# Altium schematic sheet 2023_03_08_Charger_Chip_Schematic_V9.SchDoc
size A3; SheetNumber: 1; SheetTotal: 1
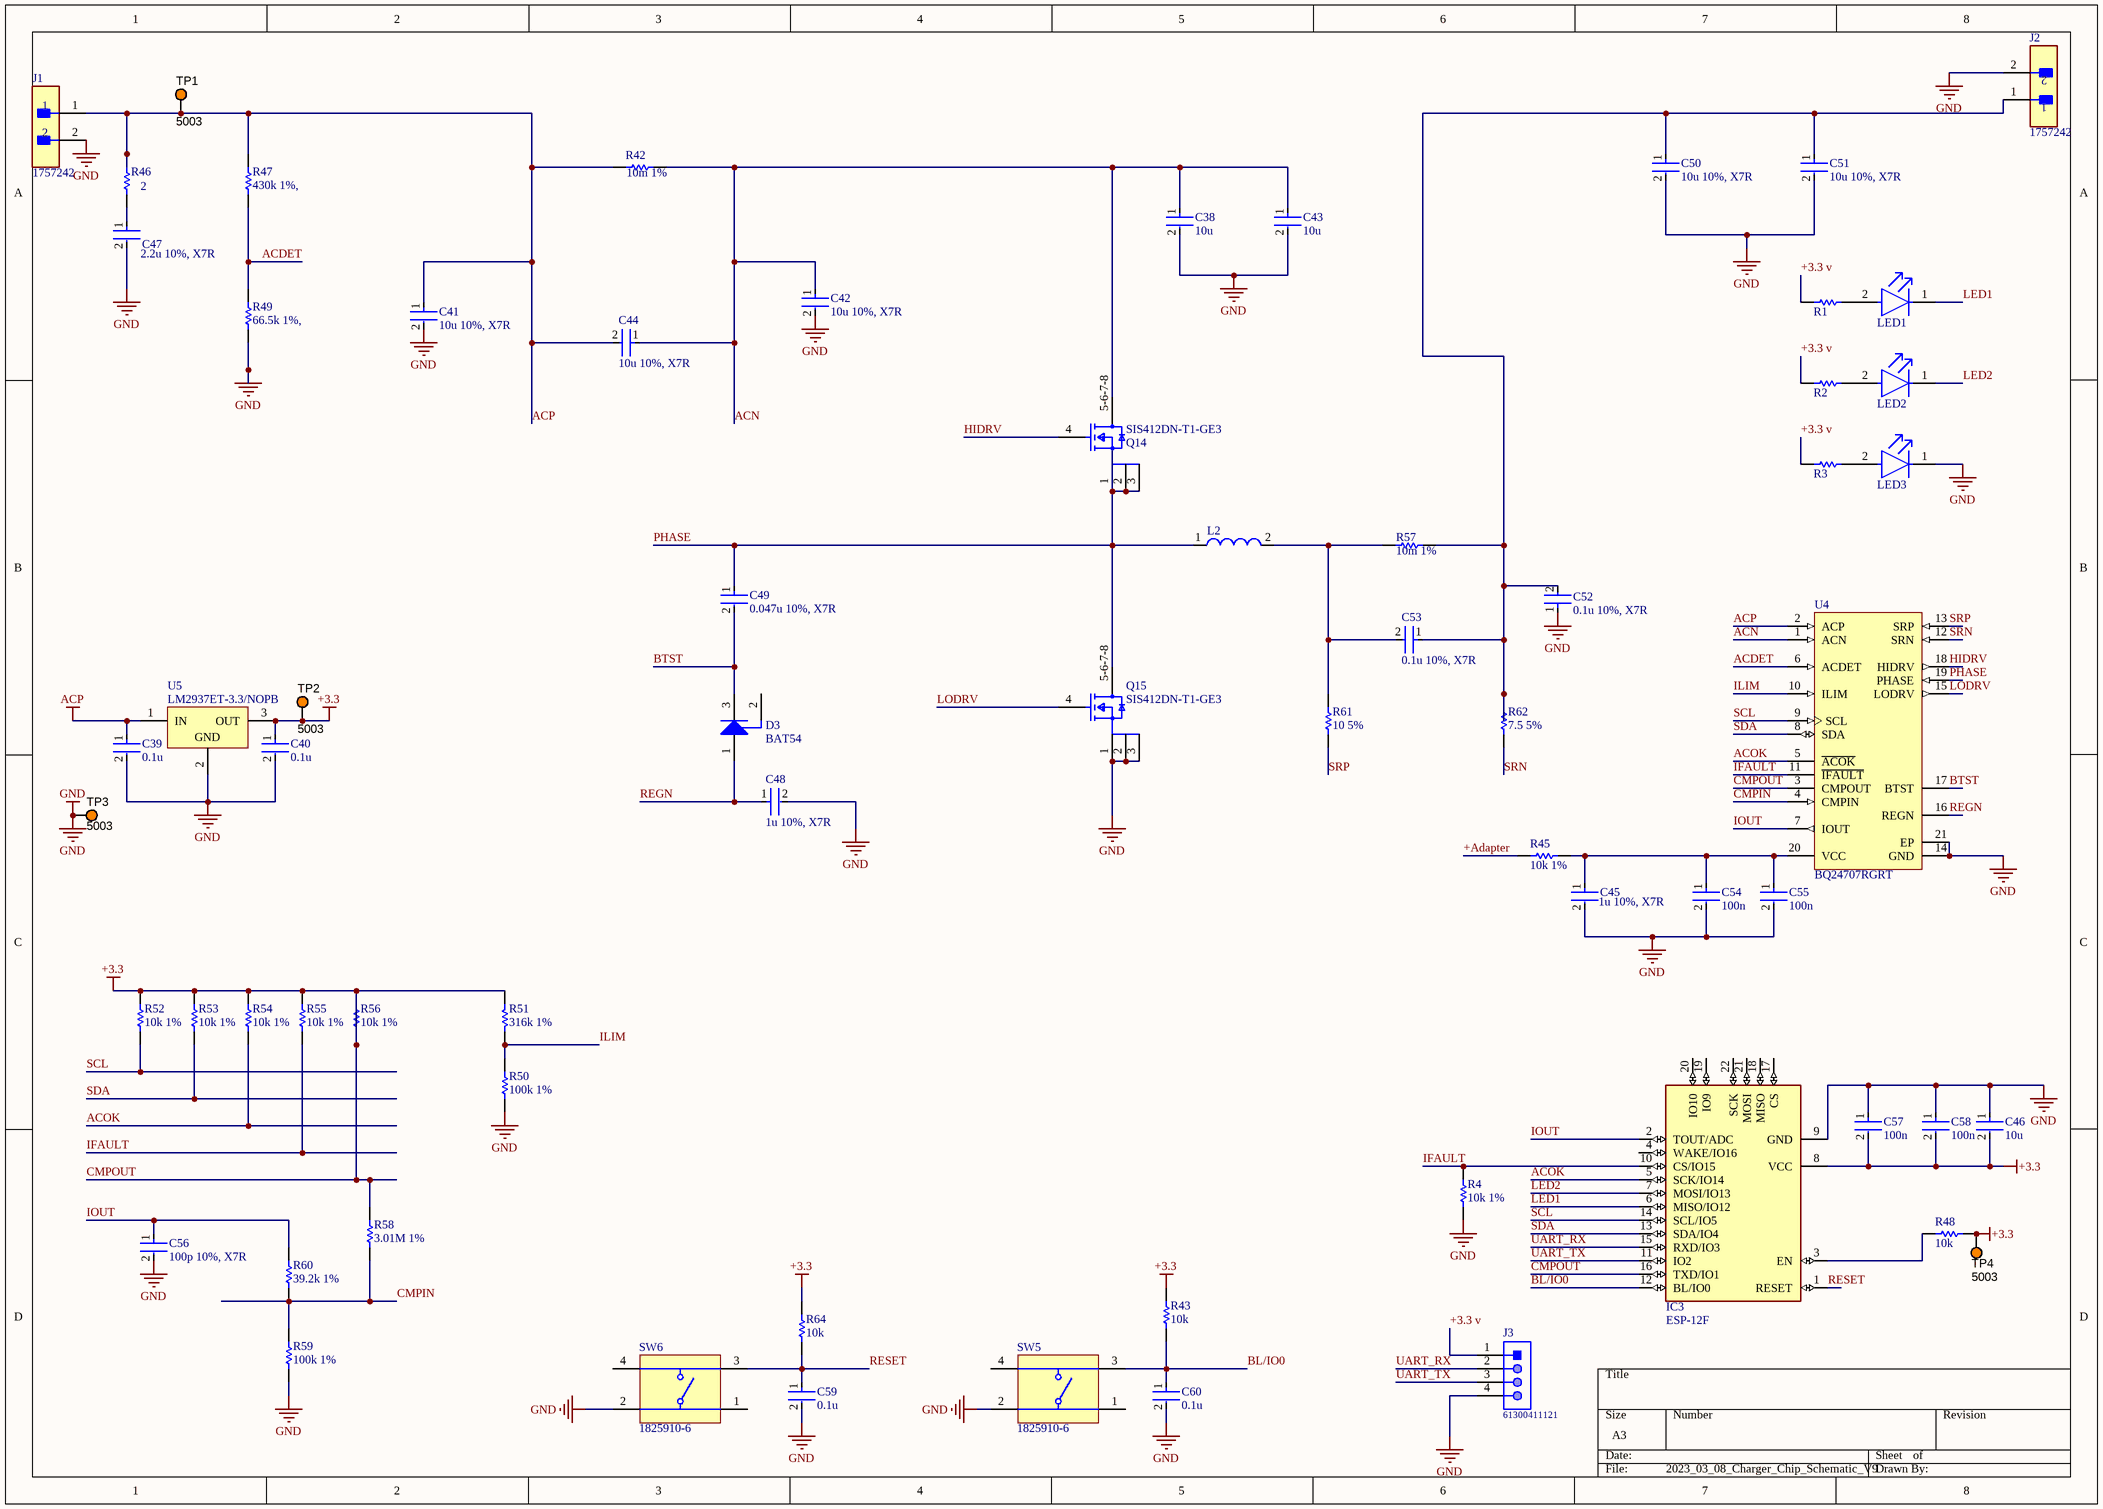
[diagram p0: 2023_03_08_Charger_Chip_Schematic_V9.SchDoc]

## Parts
C38  10u  [FP-C0603C-CF-MFG]
C39  0.1u  [FP-C0603C-CF-MFG]
C40  0.1u  [FP-C0603C-CF-MFG]
C41  10u 10%, X7R  [FP-C0603C-CF-MFG]
C42  10u 10%, X7R  [FP-C0603C-CF-MFG]
C43  10u  [FP-C0603C-CF-MFG]
C44  10u 10%, X7R  [FP-C0603C-CF-MFG]
C45  1u 10%, X7R  [FP-C0603C-CF-MFG]
C46  10u  [FP-C0603C-CF-MFG]
C47  2.2u 10%, X7R  [FP-1206-L_3_2_0_2-W_1_6_0-IPC_C]
C48  1u 10%, X7R  [FP-C0603C-CF-MFG]
C49  0.047u 10%, X7R  [FP-C0603C-CF-MFG]
C50  10u 10%, X7R  [FP-C0603C-CF-MFG]
C51  10u 10%, X7R  [FP-C0603C-CF-MFG]
C52  0.1u 10%, X7R  [FP-C0603C-CF-MFG]
C53  0.1u 10%, X7R  [FP-C0603C-CF-MFG]
C54  100n  [FP-C0603C-CF-MFG]
C55  100n  [FP-C0603C-CF-MFG]
C56  100p 10%, X7R  [FP-C0603C-CF-MFG]
C57  100n  [FP-C0603C-CF-MFG]
C58  100n  [FP-C0603C-CF-MFG]
C59  0.1u  [FP-C0603C-CF-MFG]
C60  0.1u  [FP-C0603C-CF-MFG]
D3  BAT54  [INF-SOT23_L]
IC3  ESP-12F  [ESP-12F]
J1  1757242  [FP-1757242-MFG]
J2  1757242  [FP-1757242-MFG]
J3  61300411121  [61300411121]
L2  744771004  [WE-PD-L]  (value not drawn)
LED1  APA1606SYCK  [FP-APA1606SYCK-MFG]  (value not drawn)
LED2  APA1606SYCK  [FP-APA1606SYCK-MFG]  (value not drawn)
LED3  APA1606SYCK  [FP-APA1606SYCK-MFG]  (value not drawn)
Q14  SIS412DN-T1-GE3  [FP-S16-2667-SINGLE-MFG]
Q15  SIS412DN-T1-GE3  [FP-S16-2667-SINGLE-MFG]
R1  CRCW060310K0FKEA  [RESC1609X50X30NL8T20]  (value not drawn)
R2  CRCW060310K0FKEA  [RESC1609X50X30NL8T20]  (value not drawn)
R3  CRCW060310K0FKEA  [RESC1609X50X30NL8T20]  (value not drawn)
R4  10k 1%  [RESC1609X50X30ML10T20]
R42  10m 1%  [RESC1609X50X30ML10T20]
R43  10k  [RESC1609X50X30ML10T20]
R45  10k 1%  [RESC1609X50X30ML10T20]
R46  2  [RESC1609X50X30ML10T20]
R47  430k 1%,  [RESC1609X50X30ML10T20]
R48  10k  [RESC1609X50X30ML10T20]
R49  66.5k 1%,  [RESC1609X50X30ML10T20]
R50  100k 1%  [RESC1609X50X30ML10T20]
R51  316k 1%  [RESC1609X50X30ML10T20]
R52  10k 1%  [RESC1609X50X30ML10T20]
R53  10k 1%  [RESC1609X50X30ML10T20]
R54  10k 1%  [RESC1609X50X30ML10T20]
R55  10k 1%  [RESC1609X50X30ML10T20]
R56  10k 1%  [RESC1609X50X30ML10T20]
R57  10m 1%  [RESC1609X50X30ML10T20]
R58  3.01M 1%  [RESC1609X50X30ML10T20]
R59  100k 1%  [RESC1609X50X30ML10T20]
R60  39.2k 1%  [RESC1609X50X30ML10T20]
R61  10 5%  [RESC1609X50X30ML10T20]
R62  7.5 5%  [RESC1609X50X30ML10T20]
R64  10k  [RESC1609X50X30ML10T20]
SW5  1825910-6  [TECO-1825910-6_V]
SW6  1825910-6  [TECO-1825910-6_V]
TP1  5003  [KSTN-5003]
TP2  5003  [KSTN-5003]
TP3  5003  [KSTN-5003]
TP4  5003  [KSTN-5003]
U4  BQ24707RGRT  [RGR0020A_V]
U5  LM2937ET-3.3/NOPB  [NDE0003A]

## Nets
ACP: C39.1 C41.1 C44.2 J1.1 R42.2 R46.2 R47.2 TP1.1 U4.2(ACP) U5.1(IN)
CMPOUT: C40.1 C46.2 C57.2 C58.2 IC3.8(VCC) IC3.16(TXD/IO1) R43.2 R48.1 R51.2 R52.2 R53.2 R54.2 R55.2 R56.1 R56.2 R58.2 R64.2 TP2.1 TP4.1 U4.3(CMPOUT) U5.3(OUT)  [also labelled +3.3]
GND: C38.2 C39.2 C40.2 C41.2 C42.2 C43.2 C45.2 C46.1 C47.2 C48.2 C50.2 C51.2 C52.1 C54.2 C55.2 C56.2 C57.1 C58.1 C59.2 C60.2 IC3.9(GND) J1.2 J2.2 J3.4 LED3.1(C) Q15.1(S) Q15.2(S) Q15.3(S) R4.2 R49.1 R50.1 R59.2 SW5.2 SW6.2 TP3.1 U4.14(GND) U4.21(EP) U5.2(GND)
+3.3 v: J3.1 R1.2 R2.2 R3.2
+Adapter: R45.2
ACDET: R47.1 R49.2 U4.6(ACDET)
ACN: C38.1 C42.1 C43.1 C44.1 Q14.5-6-7-8(D) R42.1 U4.1(ACN)
ACOK: IC3.5(SCK/IO14) R54.1 U4.5(~{ACOK})
BL/IO0: C60.1 IC3.12(BL/IO0) R43.1 SW5.3
BTST: C49.2 D3.3(K) U4.17(BTST)
CMPIN: R58.1 R59.1 R60.1 U4.4(CMPIN)
HIDRV: Q14.4(G) U4.18(HIDRV)
IFAULT: IC3.10(CS/IO15) R4.1 R55.1 U4.11(~{IFAULT})
ILIM: R50.2 R51.1 U4.10(ILIM)
IOUT: C56.1 IC3.2(TOUT/ADC) R60.2 U4.7(IOUT)
LED1: IC3.6(MISO/IO12) LED1.1(C)
LED2: IC3.7(MOSI/IO13) LED2.1(C)
LODRV: Q15.4(G) U4.15(LODRV)
PHASE: C49.1 L2.1 Q14.1(S) Q14.2(S) Q14.3(S) Q15.5-6-7-8(D) U4.19(PHASE)
REGN: C48.1 D3.1(A) U4.16(REGN)
RESET: C59.1 IC3.1(RESET) R64.1 SW6.3
SCL: IC3.14(SCL/IO5) R52.1 U4.9(SCL)
SDA: IC3.13(SDA/IO4) R53.1 U4.8(SDA)
SRN: R62.1 U4.12(SRN)
SRP: R61.1 U4.13(SRP)
UART_RX: IC3.15(RXD/IO3) J3.2
UART_TX: IC3.11(IO2) J3.3
NetC45_1: C45.1 C54.1 C55.1 R45.1 U4.20(VCC)
NetC47_1: C47.1 R46.1
NetC50_1: C50.1 C51.1 C52.2 C53.1 J2.1 R57.2 R62.2
NetC53_2: C53.2 L2.2 R57.1 R61.2
NetIC3_3: IC3.3(EN) R48.2
NetLED1_2: LED1.2(A) R1.1
NetLED2_2: LED2.2(A) R2.1
NetLED3_2: LED3.2(A) R3.1

Not connected (* = marked no-connect by the designer): D3 2(NC); IC3 4(WAKE/IO16) 17(CS) 18(MISO) 19(IO9) 20(IO10) 21(MOSI) 22(SCK); SW5 1 4; SW6 1 4

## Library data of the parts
C38-C46 C48-C60 = CMP-1035-02203-3: CAP CER 4700PF 50V X7R 0603; Manufacturer Part Number: C0603C472K5RACTU; Manufacturer: KEMET; Tolerance: 0.1; Capacitance: 4,700 pF; Material: Ceramic; Value: 4,700 pF; Automotive Grade: Grade 1; Temperature Coefficient: 30ppm/°C
C47 = CMP-2000-05856-2: General Purpose Ceramic Capacitor, 1206, 1nF, 5%, NP0, 30ppm/°C, 100V; Dielectric: C0G; Dissipation Factor: 2.5%; Insulation Resistance: 100GR
D3 = CMP-1182-00010-1: Silicon Schottky Diode, SOT23, Reel, Green; Manufacturer: Infineon; VF (max): 800Â mV; Configuration: Single; IF (max): 200Â mA; CT (max): 10Â pF; Green: TRUE; VR (max): 30Â V
IC3 = CMP-003-000001-1: WiFi Module; MF: AI-Thinker
J1 J2 = CMP-09399-000010-1: TERM BLOCK HDR 2POS 90DEG 5.08MM; Number of Poles: 2; Voltage Rating (DC): 320V; Number of Levels: 1; Voltage Rating: 250V; Current: 15A; Gender: Male; Current Rating: 12A; Voltage: 300V; Approvals: UL; Connector Type: Plug
J3 = CMP-1502-01064-1: THT Vertical Pin Header WR-PHD, Pitch 2.54 mm, Single Row, 4 pins; Manufacturer: Wurth Elektronik; Withstanding Voltage: 500VAC; Rated Current: 3A; Working Voltage: 250VAC; Pin Number: 4; Gender: Male; Contact Resistance: 20mOhm; Pitch: 2.54mm
L2 = CMP-0227-00698-1: SMD-Shielded Power Inductor WE-PD, L = 4.70 µH; Inductance: 4.70 ÂµH
LED1-LED3 = CMP-44529-000039-1: LED YELLOW CLEAR CHIP SMD R/A; Forward Current: 20mA; Luminous Intensity: 150mcd; Power Rating: 75mW; Viewing Angle: 110°; Dominant Wavelength: 590nm; Number of LEDs: 1; Forward Voltage: 2V
Q14 Q15 = CMP-02550-000138-1: MOSFET N-CH 30V 12A 1212-8 PPAK; Manufacturer: Vishay; Depletion Mode: False; Max Forward Diode Voltage: 1.2V; Max Junction Temp: +150°C; Input Capacitace At Vds: 435pF @ 15V; Number Of N Channels: 1; Gate Charge At Vgs: 8nC @ 10V; Threshold Vgs Max: 2.5V; Turn On Delay Time: 5ns; Drain To Source Resistance: 0.02Ω; Rthja Max: 32°C/W; Turn Off Delay Time: 15ns; Standoff Height: 0mm; Power Dissipation: 3.2W; Pulse Drain Current: 30A; Continuous Drain Current: 8.7A; Threshold Vgs Min: 1V; Gate To Source Voltage: 20V; Typ Forward Diode Voltage: 0.8V; Reverse Recovery Charge: 7nC; Transconductance: 17S
R1-R3 = CMP-1666-00005-4: Chip Resistor, 10 KOhm, +/- 1%, 100 mW, -55 to 155 degC, 0603 (1608 Metric), RoHS, Tape and Reel; Manufacturer: Vishay Semiconductor; Voltage Rating: 75 V
R4 R42 R43 R45-R62 R64 = CMP-2000-03002-1: Manufacturer: Vishay Dale; Part Number: CRCW06031K62FKEA
SW5 SW6 = CMP-1684-00021-1: Tact Switch, SPST-NO, 0.05 A, -35 to 85 degC, 4-Pin THD, RoHS, Bulk; Manufacturer: TE Connectivity; Maximum Contact Resistance: 100mOhm; Mechanical Life: 100000Cycles; Bushing Type: Unthreaded; Switch Configuration: OFF(ON); Maximum DC Voltage Rating: 24V; Contact Rating @ Voltage: 0.05A@24VDC; Actuator Color: Black; Body Orientation: Straight; Function: MomentaryContact; Illumination: N/R; Actuator Style: RoundButton; Actuator Material: PolybutyleneTerephthalate; Dielectric Strength: 500VAC; Pole Throw Configuration: SPST; Actuator Length: 1.4mm
TP1-TP4 = CMP-002-00037-2: Test Point, Orange, Height 4.6 mm, Tail Length 3 mm, 1-Pin THD, RoHS; Manufacturer: Keystone
U4 = CMP-0321-00247-2: High-Frequency, High Performance SMBus Charge Controller, 4.5 V, -40 to 85 degC, 20-pin VQFN (RGR), Green (RoHS & no Sb/Br); Manufacturer: Texas Instruments; SubFamily: Battery Charge Management; NiMH: N; Vin(Min)(V): 4.5
U5 = CMP-0062-02520-3: 400mA and 500mA Voltage Regulator, 3-pin TO-220, Pb-Free; Manufacturer: Texas Instruments; CompType: LDO IC; PackageTopMarking: NSUZXYTTE#*LM2937ET*-3.3; PowerWise: N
